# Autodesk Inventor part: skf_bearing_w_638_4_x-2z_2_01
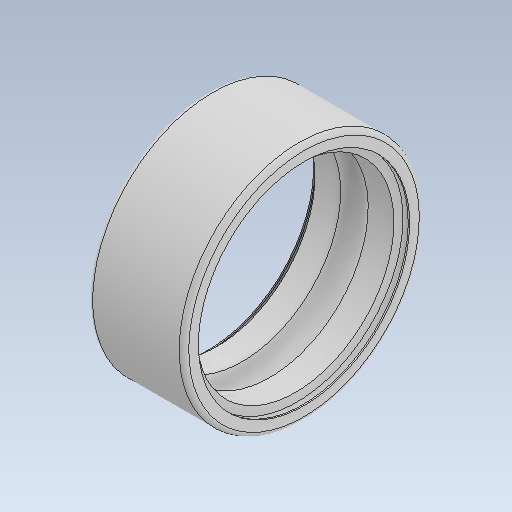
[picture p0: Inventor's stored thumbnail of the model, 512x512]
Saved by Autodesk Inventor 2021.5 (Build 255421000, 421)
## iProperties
Created: 2023-12
Part Number: skf_bearing_w_638_4_x-2z_2_01
Checked By: TraceParts S.A.
Material: Generic
Catalog Web Link: www.traceparts.com
Document SubType Name: Modeling
Designer: TraceParts
Density: 1 g/cm^3
Appearance: Default
Company: TraceParts S.A.
Author: TraceParts
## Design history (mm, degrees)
feature "skf_bearing_w_638_4_x-2z_2_01.ipt"
body "Solid1"
